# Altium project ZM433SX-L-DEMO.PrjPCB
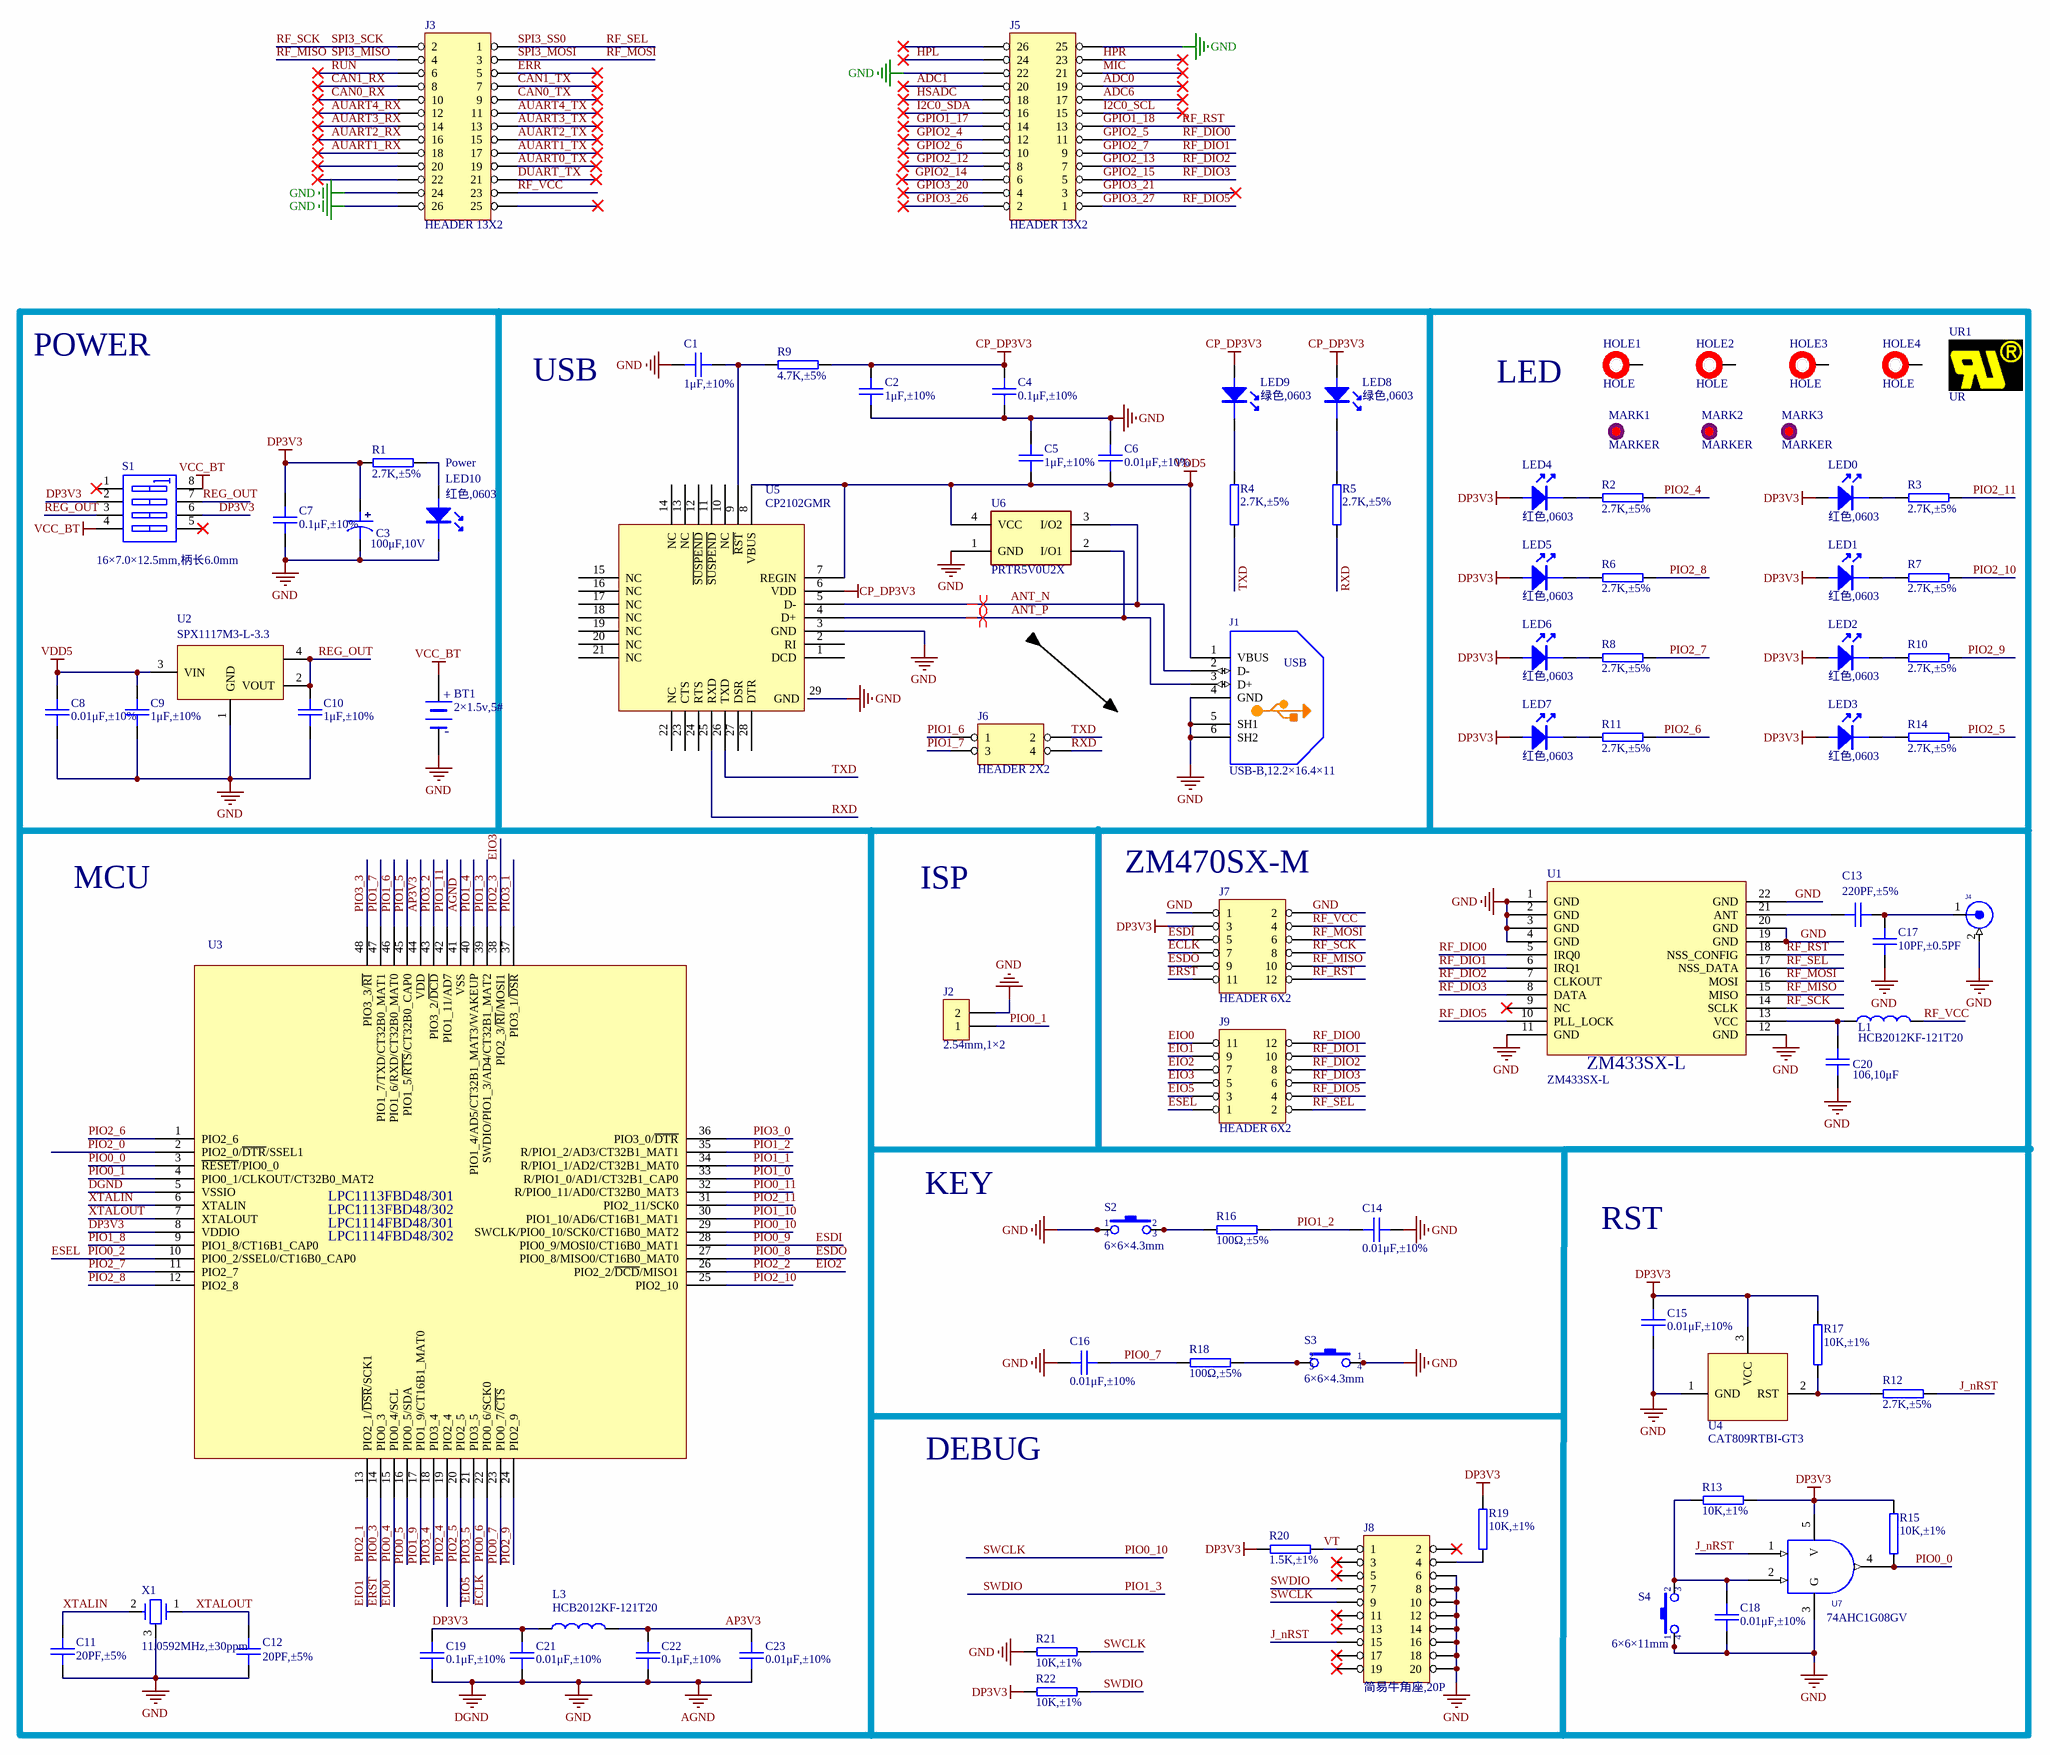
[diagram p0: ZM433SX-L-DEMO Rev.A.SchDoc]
1 sheet, 88 parts. Net scope: global (net labels, ports and power ports of the same name join across sheets).
Board file: ZM433SX-L-DEMO Rev.A .PcbDoc

## Sheet ZM433SX-L-DEMO Rev.A.SchDoc
size A2

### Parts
BT1  2×1.5v,5#  [BAT-5#X2]
C1  1μF,±10%  [0402C]
C2  1μF,±10%  [0402C]
C3  100μF,10V  [CAP-C]
C4  0.1μF,±10%  [0402C]
C5  1μF,±10%  [0402C]
C6  0.01μF,±10%  [0402C]
C7  0.1μF,±10%  [0402C]
C8  0.01μF,±10%  [0402C]
C9  1μF,±10%  [0402C]
C10  1μF,±10%  [0402C]
C11  20PF,±5%  [0402C]
C12  20PF,±5%  [0402C]
C13  220PF,±5%  [0402C]
C14  0.01μF,±10%  [0402C]
C15  0.01μF,±10%  [0402C]
C16  0.01μF,±10%  [0402C]
C17  10PF,±0.5PF  [0402C]  (no BOM)
C18  0.01μF,±10%  [0402C]
C19  0.1μF,±10%  [0402C]
C20  106,10μF  [0805C]
C21  0.01μF,±10%  [0402C]
C22  0.1μF,±10%  [0402C]
C23  0.01μF,±10%  [0402C]
HOLE1  HOLE  [HOLE-2.2]  (no BOM)
HOLE2  HOLE  [HOLE-2.2]  (no BOM)
HOLE3  HOLE  [HOLE-2.2]  (no BOM)
HOLE4  HOLE  [HOLE-2.2]  (no BOM)
J1  value USB-B,12.2×16.4×11  [USB-B-1650X1105X1204]  (hidden comment: USB)
J2  value 2.54mm,1×2  [SIP-2]  (hidden comment: CON2)  (no BOM)
J3  HEADER 13X2  [IDC-26]  (no BOM)
J4  BNC Connector3  [BNC-2C]  (value not drawn)
J5  HEADER 13X2  [IDC-26]  (no BOM)
J6  HEADER 2X2  [idc-4]
J7  HEADER 6X2  [idc-12]
J8  value 简易牛角座,20P  [IDE-20]  (hidden comment: HEADER 10X2)
J9  HEADER 6X2  [idc-12]
L1  value HCB2012KF-121T20  [L0805]  (hidden comment: INDUCTOR1)
L3  value HCB2012KF-121T20  [L0805]  (hidden comment: INDUCTOR1)
LED0  value 红色,0603  [LED-0603]  (hidden comment: Power)
LED1  value 红色,0603  [LED-0603]  (hidden comment: Power)
LED2  value 红色,0603  [LED-0603]  (hidden comment: Power)
LED3  value 红色,0603  [LED-0603]  (hidden comment: Power)
LED4  value 红色,0603  [LED-0603]  (hidden comment: Power)
LED5  value 红色,0603  [LED-0603]  (hidden comment: Power)
LED6  value 红色,0603  [LED-0603]  (hidden comment: Power)
LED7  value 红色,0603  [LED-0603]  (hidden comment: Power)
LED8  value 绿色,0603  [LED-0603]  (hidden comment: LED1)
LED9  value 绿色,0603  [LED-0603]  (hidden comment: LED1)
LED10  Power  value 红色,0603  [LED-0603]
MARK1  MARKER  [MARKER-C-1.0M]  (no BOM)
MARK2  MARKER  [MARKER-C-1.0M]  (no BOM)
MARK3  MARKER  [MARKER-C-1.0M]  (no BOM)
R1  2.7K,±5%  [0402R]
R2  2.7K,±5%  [0402R]
R3  2.7K,±5%  [0402R]
R4  2.7K,±5%  [0402R]
R5  2.7K,±5%  [0402R]
R6  2.7K,±5%  [0402R]
R7  2.7K,±5%  [0402R]
R8  2.7K,±5%  [0402R]
R9  4.7K,±5%  [0402R]
R10  2.7K,±5%  [0402R]
R11  2.7K,±5%  [0402R]
R12  2.7K,±5%  [0402R]
R13  10K,±1%  [0402R]
R14  2.7K,±5%  [0402R]
R15  10K,±1%  [0402R]
R16  100Ω,±5%  [0402R]
R17  10K,±1%  [0402R]
R18  100Ω,±5%  [0402R]
R19  10K,±1%  [0402R]
R20  1.5K,±1%  [0402R]
R21  10K,±1%  [0402R]
R22  10K,±1%  [0402R]
S1  value 16×7.0×12.5mm,柄长6.0mm  [SW2-3-2.0]  (hidden comment: SW DIP-4)
S2  value 6×6×4.3mm  [KEY-6A]  (hidden comment: SW-PB4P)
S3  value 6×6×4.3mm  [KEY-6A]  (hidden comment: SW-PB4P)
S4  value 6×6×11mm  [KEY-6A]  (hidden comment: SW-PB4P)
U1  ZM433SX-L  [ZM470SX-M]
U2  value SPX1117M3-L-3.3  [SOT-223]  (hidden comment: SPX1117M3-L/TR)
U3  LPC1114FBD48/302  [QFP50P900X900X120-48N]  (value not drawn)
U4  CAT809RTBI-GT3  [SOT-23]
U5  value CP2102GMR  [QFN50P500X500X100-29AN]  (hidden comment: CP2102)
U6  PRTR5V0U2X  [SOT-143]
U7  value 74AHC1G08GV  [SOT-23-5]  (hidden comment: 74AHC1G08)
UR1  UR  [ZY_UR-3X2]  (no BOM)
X1  value 11.0592MHz,±30ppm  [XTAL2-1120X470X3680]  (hidden comment: XTAL2)

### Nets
AGND: BT1.2(-) C1.1 C2.1 C3.2 C4.2 C5.2 C6.2 C7.2 C8.1 C9.2 C10.2 C11.2 C12.2 C14.2 C15.2 C16.1 C17.2 C18.2 C19.2 C20.2 C21.1 C22.2 C23.1 J1.4(GND) J1.5(SH1) J1.6(SH2) J2.2 J3.24 J3.26 J4.2 J5.22 J5.25 J7.1 J7.2 J8.6 J8.8 J8.10 J8.12 J8.14 J8.16 J8.18 J8.20 LED10.2 R21.1 S2.1 S2.4 S3.1 S3.4 S4.1 S4.4 U1.1(GND) U1.2(GND) U1.3(GND) U1.4(GND) U1.11(GND) U1.12(GND) U1.19(GND) U1.20(GND) U1.22(GND) U2.1(GND) U3.5(VSSIO) U3.41(VSS) U4.1(GND) U5.3(GND) U5.29(GND) U6.1(GND) U7.3(G) X1.3(G)  [also labelled DGND, GND]
CP_DP3V3: C2.2 C4.1 LED8.1 LED9.1 R9.2 U5.6(VDD)
DP3V3: C3.1 C7.1 C15.1 C19.1 C21.2 J7.3 L3.1 LED0.1 LED1.1 LED2.1 LED3.1 LED4.1 LED5.1 LED6.1 LED7.1 R1.2 R13.1 R15.2 R17.2 R19.1 R20.1 R22.1 S1.2(A2) S1.6(B3) U3.8(VDDIO) U4.3(VCC) U7.5(V)
VCC_BT: BT1.1(+) S1.4(A4) S1.8(B1)
VDD5: C5.1 C6.1 C8.2 C9.1 J1.1(VBUS) U2.3(VIN) U5.7(REGIN) U5.8(VBUS) U6.4(VCC)
ADC0: J5.19
ADC1: J5.20
ADC6: J5.17
ANT_N: J1.2(D-) U5.5(D-) U6.3(I/O2)
ANT_P: J1.3(D+) U5.4(D+) U6.2(I/O1)
AP3V3: C22.1 C23.2 L3.2 U3.44(VDD)
AUART0_TX: J3.19
AUART1_RX: J3.18
AUART1_TX: J3.17
AUART2_RX: J3.16
AUART2_TX: J3.15
AUART3_RX: J3.14
AUART3_TX: J3.13
AUART4_RX: J3.12
AUART4_TX: J3.11
CAN0_RX: J3.10
CAN0_TX: J3.9
CAN1_RX: J3.8
CAN1_TX: J3.7
DUART_TX: J3.21
ECLK: J7.7 U3.22(PIO0_6/SCK0)  [also labelled PIO0_6]
EIO0: J9.11 U3.15(PIO0_4/SCL)  [also labelled PIO0_4]
EIO1: J9.9 U3.13(PIO2_1/~{DSR}/SCK1)  [also labelled PIO2_1]
EIO2: J9.7 U3.26(PIO2_2/~{DCD}/MISO1)  [also labelled PIO2_2]
EIO3: J9.5 U3.38(PIO2_3/~{RI}/MOSI1)  [also labelled PIO2_3]
EIO5: J9.3 U3.21(PIO3_5)  [also labelled PIO3_5]
ERR: J3.5
ERST: J7.11 U3.14(PIO0_3)  [also labelled PIO0_3]
ESDI: J7.5 U3.28(PIO0_9/MOSI0/CT16B0_MAT1)  [also labelled PIO0_9]
ESDO: J7.9 U3.27(PIO0_8/MISO0/CT16B0_MAT0)  [also labelled PIO0_8]
ESEL: J9.1 U3.10(PIO0_2/SSEL0/CT16B0_CAP0)  [also labelled PIO0_2]
GPIO1_17: J5.14
GPIO1_18: J5.13 J7.12 U1.18(NSS_CONFIG)  [also labelled RF_RST]
GPIO2_4: J5.12
GPIO2_5: J5.11 J9.12 U1.5(IRQ0)  [also labelled RF_DIO0]
GPIO2_6: J5.10
GPIO2_7: J5.9 J9.10 U1.6(IRQ1)  [also labelled RF_DIO1]
GPIO2_12: J5.8
GPIO2_13: J5.7 J9.8 U1.7(CLKOUT)  [also labelled RF_DIO2]
GPIO2_14: J5.6
GPIO2_15: J5.5 J9.6 U1.8(DATA)  [also labelled RF_DIO3]
GPIO3_20: J5.4
GPIO3_21: J5.3
GPIO3_26: J5.2
GPIO3_27: J5.1 J9.4 U1.10(PLL_LOCK)  [also labelled RF_DIO5]
HPL: J5.24
HPR: J5.23
HSADC: J5.18
I2C0_SCL: J5.15
I2C0_SDA: J5.16
J_nRST: J8.15 R12.1 U7.1(IN_B)
MIC: J5.21
PIO0_0: R15.1 U3.3(~{RESET}/PIO0_0) U7.4(OUT_Y)
PIO0_1: J2.1 U3.4(PIO0_1/CLKOUT/CT32B0_MAT2)
PIO0_5: U3.16(PIO0_5/SDA)
PIO0_7: C16.2 R18.1 U3.23(PIO0_7/~{CTS})
PIO0_10: J8.9 R21.2 U3.29(SWCLK/PIO0_10/SCK0/CT16B0_MAT2)  [also labelled SWCLK]
PIO0_11: U3.32(R/PIO0_11/AD0/CT32B0_MAT3)
PIO1_0: U3.33(R/PIO1_0/AD1/CT32B1_CAP0)
PIO1_1: U3.34(R/PIO1_1/AD2/CT32B1_MAT0)
PIO1_2: C14.1 R16.2 U3.35(R/PIO1_2/AD3/CT32B1_MAT1)
PIO1_3: J8.7 R22.2 U3.39(SWDIO/PIO1_3/AD4/CT32B1_MAT2)  [also labelled SWDIO]
PIO1_4: U3.40(PIO1_4/AD5/CT32B1_MAT3/WAKEUP)
PIO1_5: U3.45(PIO1_5/~{RTS}/CT32B0_CAP0)
PIO1_6: J6.1 U3.46(PIO1_6/RXD/CT32B0_MAT0)
PIO1_7: J6.3 U3.47(PIO1_7/TXD/CT32B0_MAT1)
PIO1_8: U3.9(PIO1_8/CT16B1_CAP0)
PIO1_9: U3.17(PIO1_9/CT16B1_MAT0)
PIO1_10: U3.30(PIO1_10/AD6/CT16B1_MAT1)
PIO1_11: U3.42(PIO1_11/AD7)
PIO2_0: U3.2(PIO2_0/~{DTR}/SSEL1)
PIO2_4: R2.2 U3.19(PIO2_4)
PIO2_5: R14.1 U3.20(PIO2_5)
PIO2_6: R11.1 U3.1(PIO2_6)
PIO2_7: R8.1 U3.11(PIO2_7)
PIO2_8: R6.1 U3.12(PIO2_8)
PIO2_9: R10.1 U3.24(PIO2_9)
PIO2_10: R7.1 U3.25(PIO2_10)
PIO2_11: R3.2 U3.31(PIO2_11/SCK0)
PIO3_0: U3.36(PIO3_0/~{DTR})
PIO3_1: U3.37(PIO3_1/~{DSR})
PIO3_2: U3.43(PIO3_2/~{DCD})
PIO3_3: U3.48(PIO3_3/~{RI})
PIO3_4: U3.18(PIO3_4)
REG_OUT: C10.1 S1.3(A3) S1.7(B2) U2.2(VOUT) U2.4
RF_MISO: J3.4 J7.10 U1.15(MISO)  [also labelled SPI3_MISO]
RF_MOSI: J3.3 J7.6 U1.16(MOSI)  [also labelled SPI3_MOSI]
RF_SCK: J3.2 J7.8 U1.14(SCLK)  [also labelled SPI3_SCK]
RF_SEL: J3.1 J9.2 U1.17(NSS_DATA)  [also labelled SPI3_SS0]
RF_VCC: J3.23 J7.4 L1.2
RUN: J3.6
RXD: J6.4 R5.1 U5.25(RXD)
TXD: J6.2 R4.1 U5.26(TXD)
VT: J8.1 R20.2
XTALIN: C11.1 U3.6(XTALIN) X1.2
XTALOUT: C12.1 U3.7(XTALOUT) X1.1
NetC1_2: C1.2 R9.1 U5.9(~{RST})
NetC13_1: C13.1 U1.21(ANT)
NetC13_2: C13.2 C17.1 J4.1
NetC18_1: C18.1 R13.2 S4.2 S4.3 U7.2(IN_A)
NetC20_1: C20.1 L1.1 U1.13(VCC)
NetJ8_4: J8.4 R19.2
NetLED0_2: LED0.2 R3.1
NetLED1_2: LED1.2 R7.2
NetLED2_2: LED2.2 R10.2
NetLED3_2: LED3.2 R14.2
NetLED4_2: LED4.2 R2.1
NetLED5_2: LED5.2 R6.2
NetLED6_2: LED6.2 R8.2
NetLED7_2: LED7.2 R11.2
NetLED8_2: LED8.2 R5.2
NetLED9_2: LED9.2 R4.2
NetLED10_1: LED10.1 R1.1
NetR12_2: R12.2 R17.1 U4.2(RST)
NetR16_1: R16.1 S2.2 S2.3
NetR18_2: R18.2 S3.2 S3.3

Not connected (* = marked no-connect by the designer): HOLE1 1; HOLE2 1; HOLE3 1; HOLE4 1; J3 20* 22* 25; J5 26*; J8 2* 3* 5* 11* 13* 17* 19*; MARK1 0; MARK2 0; MARK3 0; S1 1(A1)* 5(B4)*; U1 9(NC)*; U5 1(DCD) 2(RI) 10(NC) 11(~{SUSPEND}) 12(~{SUSPEND}) 13(NC) 14(NC) 15(NC) 16(NC) 17(NC) 18(NC) 19(NC) 20(NC) 21(NC) 22(NC) 23(CTS) 24(RTS) 27(DSR) 28(DTR)

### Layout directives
differential pair: ANT_N, ANT_P

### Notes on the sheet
- POWER
- USB
- LED
- MCU
- ISP
- (near J7) ZM470SX-M
- KEY
- RST
- DEBUG

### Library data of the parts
BT1 = 1.20.03.0005: 名称: 电池盒; 贴片和直插: THT; PCB备注: 160623 pcb   by hcj; 器件优选方案: 正常状态，可以选用
C1 C2 C5 C9 C10 = 1.02.17.0007: 1μF,±10%,6.3V,X5R,0402,RoHS; 名称: 电容; 封装: 0402; 设备封装名称: C0402_1uF_X5R_6.3V_10%; 贴片和直插: SMT; 器件优选方案: 状态正常
C3 = 1.02.05.0016: 100μF,10V,C型,,AVX,RoHS; 名称: 钽电容; 设备封装名称: C_100uF_10V; 贴片和直插: SMT
C4 C7 C19 C22 = 1.02.17.0020: 0.1μF,±10%,X5R,25V,0402,RoHS; 名称: 电容; 封装: 0402; 设备封装名称: C0402_0.1uF_X5R_25V_10%; 贴片和直插: SMT; 器件优选方案: 状态正常
C6 C8 C14-C16 C18 C21 C23 = 1.02.17.0019: 0.01μF,±10%,X7R,50V,0402,RoHS; 名称: 电容; 封装: 0402; 设备封装名称: C0402_0.01uF_X7R_50V_10%; 贴片和直插: SMT; 器件优选方案: 状态正常
C11 C12 = 1.02.17.0009: 20PF,±5%,50V,COG,0402,RoHS; 名称: 电容; 封装: 0402; 设备封装名称: C0402_20PF_COG_50V_5%; 贴片和直插: SMT
C13 = 1.02.17.0035: 220PF,±5%,50V,NPO,0402,RoHS; 名称: 电容; 封装: 0402; 设备封装名称: C0402_220PF_NPO_50V_5%; 贴片和直插: SMT; 器件优选方案: 状态正常
C17 = 1.02.17.0008: 10PF,±0.5PF,50V,COG,0402,TDK,RoHS; 名称: 电容; 封装: 0402; 设备封装名称: C0402_10PF_COG_50V_+-0.5PF; 贴片和直插: SMT; 器件优选方案: 状态正常
C20 = 1.02.02.0055: 106,10μF,±10%,10V,X5R,0805,RoHS; 名称: 电容; 封装: 0805; 设备封装名称: C0805_106_X5R_10V_10%; 贴片和直插: SMT
J1 = 1.10.05.0010: USB-B,12.2×16.4×11,90°,RoHS; Text Field1: 50; Text Field2: 60; 名称: USB插座; 贴片和直插: THT; PCB备注: Fxhm-Sjj-Tlq-141208
J2 = 1.10.03.0084: 2.54mm,1×2,180°,H=8.5mm,2.4/3.0,镀全金3U,,RoHS; 名称: 排母; 贴片和直插: THT
J4 = 1.10.05.0129: SMA,外螺纹,孔,SMD,RoHS; 名称: 射频连接器; 贴片和直插: THT; PCB备注: PCBlmd150108修改插件封装；BNC-2C为侧位贴片封装，BNC-2mini为正常位插件封装
J8 = 1.10.04.0003: 简易牛角座,20P,180°,黑色,,*; 名称: IDC插座; 贴片和直插: THT
L1 L3 = 1.03.03.0020: HCB2012KF-121T20,0805,信和达,RoHS; 名称: 磁珠; 封装: 0805; 贴片和直插: SMT
LED0-LED7 LED10 = 1.04.05.0008: 红色,0603,0603,*,RoHS; 名称: 发光二极管; 封装: 0603; 设备封装名称: LED0603-RED; 贴片和直插: SMT; 器件优选方案: 优先选用
LED8 LED9 = 1.04.05.0009: 绿色,0603,0603,*,RoHS; 名称: 发光二极管; 封装: 0603; 设备封装名称: LED0603-GREEN; 贴片和直插: SMT; 器件优选方案: 优先选用
R1-R8 R10-R12 R14 = 1.01.17.0062: 2.7K,±5%,1/16W,0402,RoHS; 名称: 电阻; 封装: 0402; 设备封装名称: R0402_2.7K; 厂商: Ralec; 贴片和直插: SMT; 器件优选方案: 状态正常
R9 = 1.01.17.0019: 4.7K,±5%,0402,RALEC,RoHS; 名称: 电阻; 封装: 0402; 设备封装名称: R0402_4.7K; 贴片和直插: SMT; 器件优选方案: 状态正常
R13 R15 R17 R19 R21 R22 = 1.01.17.0034: 10K,±1%,0402,RALEC,RoHS; 名称: 电阻; 封装: 0402; 设备封装名称: R0402_10K_1%; 贴片和直插: SMT
R16 R18 = 1.01.17.0012: 100Ω,±5%,0402,RALEC,RoHS; 名称: 电阻; 封装: 0402; 设备封装名称: R0402_100R; 贴片和直插: SMT; 器件优选方案: 状态正常
R20 = 1.01.17.0011: 1.5K,±1%,0402,RALEC,RoHS; 名称: 电阻; 封装: 0402; 设备封装名称: R0402_1.5K_1%; 贴片和直插: SMT
S1 = 1.09.07.0014: 16×7.0×12.5mm,柄长6.0mm,单刀三掷开关; 名称: 拨动开关; 贴片和直插: THT
S2 S3 = 1.09.02.0001: 6×6×4.3mm,,*; 名称: 轻触按键; 贴片和直插: THT
S4 = 1.09.02.0012: 6×6×11mm; 名称: 轻触按键; 贴片和直插: THT
U1 = 2.08.01.0534: ZM433SX-L V1.00; 名称: 无线模块; PCB备注: 160613 hcj; 器件优选方案: 正常状态，可以选用
U2 = 1.05.09.0025: SPX1117M3-L-3.3,SOT-223,EXAR,RoHS; 名称: IC; 设备封装名称: SOT-223_SPX1117M3-L-3.3; 贴片和直插: SMT
U3 = 1.05.02.0118: LPC1114FBD48/302,LQFP-48,NXP,RoHS; 名称: IC; 贴片和直插: SMT
U4 = 1.05.07.0011: CAT809RTBI-GT3,SOT-23,ON,RoHS; 名称: IC; 设备封装名称: SOT-23_CAT809RTBI-T; 贴片和直插: SMT; 器件优选方案: 量产物料,优先选用
U5 = 1.05.08.0037: CP2102GMR,QFN-28,Silicon Labs; 名称: IC; 设备封装名称: QFN-28_CP2102GMR; 贴片和直插: SMT
U6 = 1.05.10.0153: PRTR5V0U2X,SOT-143B,NXP,RoHS; 名称: IC; 设备封装名称: SOT-143B_PRTR5V0U2X; 贴片和直插: SMT
U7 = 1.05.05.0093: 74AHC1G08GV,SOT-753,NXP,RoHS; Manufacturer: PHILIPS; ID: 77; 名称: IC; 设备封装名称: SOT-753_74AHC1G08GV; 贴片和直插: SMT
X1 = 1.07.02.0010: 11.0592MHz,±30ppm,20pF,-40~85℃,±30ppm,HC-49/S,*,RoHS; 名称: 晶体; 设备封装名称: 11.0592MHz,±30PPM,20PF,HC-49US,工业级; 型号: 11.0592MHz,±30ppm,20pF,-40~85,±30ppm; 贴片和直插: THT; PCB备注: 焊盘孔径改为34mil，两脚间距改为4.88mm，Fwrj-Shcj-Tlq-141224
